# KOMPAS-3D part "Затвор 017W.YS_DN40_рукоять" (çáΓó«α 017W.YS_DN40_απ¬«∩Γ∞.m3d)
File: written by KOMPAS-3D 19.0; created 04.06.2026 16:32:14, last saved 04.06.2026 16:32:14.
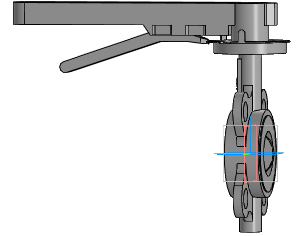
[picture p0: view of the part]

Document properties: Автор: Энергия; Полное имя файла: ..\..\..\3d для проектировщиков\017W разные\x.x Тип 017W.Y(S) Затвор дисковый поворотный межфланцевый\Затвор 017W.Y(S)_DN32-DN300_рукоять\Затвор 017W.YS_DN40_рукоять.a3d

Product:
- Part/product: Затвор 017W.YS_DN40_рукоять
    Масса: 3.04015

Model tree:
1. Операция без истории:1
